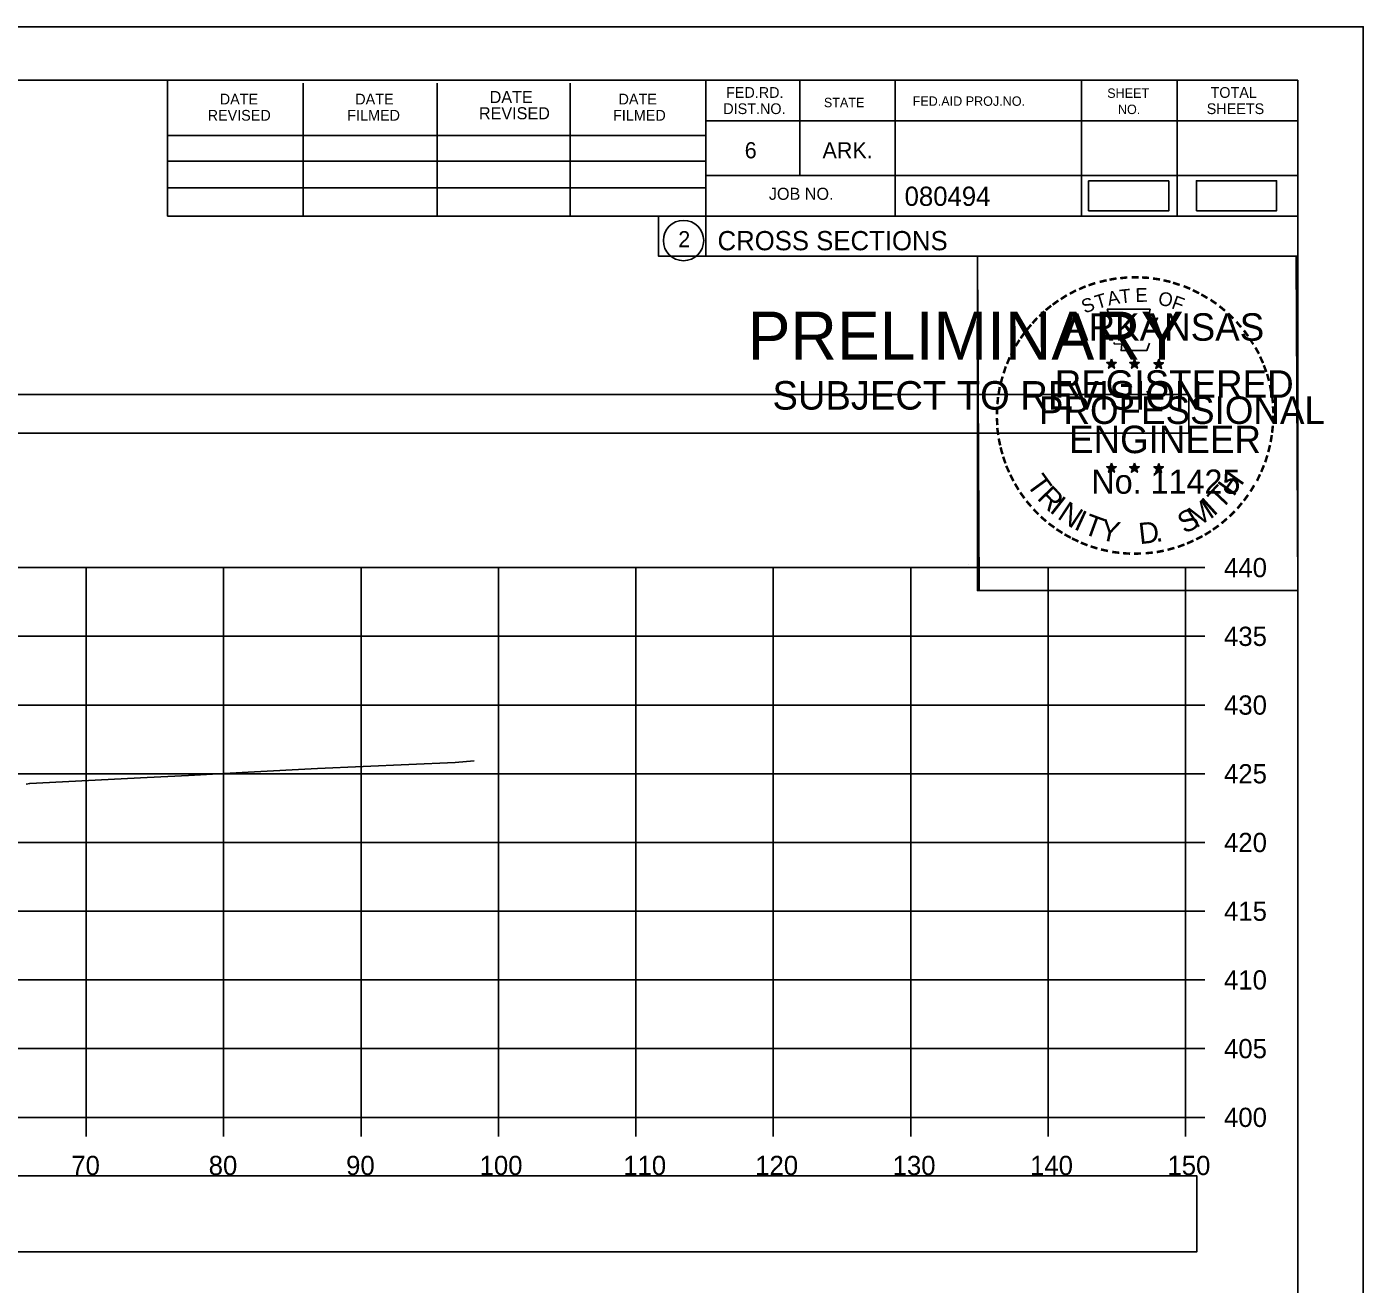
# Model space of a CAD drawing. Extents: x 1376273 to 1384221, y 378927 to 384592.
# Drawn here: x 1378290.1 to 1378387.4, y 382153.7 to 382245.2 of the extents above; entities that cross this region are included whole.
import ezdxf

# ---------------------------------------------------------------- set-up
doc = ezdxf.new("R2010")
doc.units = 0
for name, color, linetype in [('R_Axis', 7, 'Continuous'), ('R_Axis Annot', 7, 'Continuous'), ('R_Border', 7, 'Continuous'), ('R_Border PE', 7, 'Continuous'), ('R_Border Prem', 7, 'Continuous'), ('R_Drive', 7, 'Continuous'), ('R_Exist Surface', 7, 'Continuous'), ('R_Grid', 7, 'Continuous'), ('R_No Plot', 7, 'Continuous')]:
    doc.layers.add(name, color=color, linetype=linetype)

msp = doc.modelspace()

# ---------------------------------------------------------------- linework, layer by layer
at = {"layer": 'R_Axis'}
for p, q in [((1378374.457, 382165.86), (1378374.457, 382205.86)), ((1378375.857, 382205.86), (1378374.457, 382205.86)), ((1378375.857, 382200.86), (1378374.457, 382200.86)), ((1378375.857, 382195.86), (1378374.457, 382195.86)), ((1378375.857, 382190.86), (1378374.457, 382190.86)), ((1378375.857, 382185.86), (1378374.457, 382185.86)), ((1378375.857, 382180.86), (1378374.457, 382180.86)), ((1378375.857, 382175.86), (1378374.457, 382175.86)), ((1378375.857, 382170.86), (1378374.457, 382170.86)), ((1378074.457, 382165.86), (1378374.457, 382165.86)), ((1378294.457, 382164.46), (1378294.457, 382165.86)), ((1378304.457, 382164.46), (1378304.457, 382165.86)), ((1378314.457, 382164.46), (1378314.457, 382165.86)), ((1378324.457, 382164.46), (1378324.457, 382165.86)), ((1378334.457, 382164.46), (1378334.457, 382165.86)), ((1378344.457, 382164.46), (1378344.457, 382165.86)), ((1378354.457, 382164.46), (1378354.457, 382165.86)), ((1378364.457, 382164.46), (1378364.457, 382165.86)), ((1378374.457, 382164.46), (1378374.457, 382165.86)), ((1378375.857, 382165.86), (1378374.457, 382165.86))]:
    msp.add_line(p, q, dxfattribs=at)
at = {"layer": 'R_Axis Annot'}
for points in [[(1378072.9, 382215.644), (1378374.702, 382215.644), (1378374.702, 382218.461), (1378072.9, 382218.461)], [(1378073.479, 382156.081), (1378375.281, 382156.081), (1378375.281, 382161.603), (1378073.479, 382161.603)]]:
    msp.add_lwpolyline(points, close=True, dxfattribs=at)
at = {"layer": 'R_Border'}
for p, q in [((1378066.457, 382241.32), (1378382.637, 382241.32)), ((1378300.377, 382231.44), (1378300.377, 382241.32)), ((1378310.237, 382231.44), (1378310.237, 382241.12)), ((1378319.997, 382231.44), (1378319.997, 382241.12)), ((1378329.677, 382231.44), (1378329.677, 382241.12)), ((1378339.537, 382241.32), (1378339.537, 382228.52)), ((1378346.377, 382241.32), (1378346.377, 382234.38)), ((1378353.317, 382241.32), (1378353.317, 382231.44)), ((1378366.897, 382241.32), (1378366.897, 382231.44)), ((1378373.837, 382241.32), (1378373.837, 382231.44)), ((1378382.637, 382035.86), (1378382.637, 382241.32)), ((1378382.637, 382238.38), (1378339.537, 382238.38)), ((1378382.637, 382238.4), (1378382.637, 382238.4)), ((1378300.377, 382237.3), (1378339.537, 382237.3)), ((1378300.377, 382235.44), (1378339.537, 382235.44)), ((1378382.637, 382234.38), (1378339.537, 382234.38)), ((1378342.497, 382234.38), (1378382.637, 382234.38)), ((1378300.377, 382231.44), (1378300.377, 382233.5)), ((1378300.377, 382233.5), (1378339.537, 382233.5)), ((1378382.637, 382231.44), (1378300.377, 382231.44)), ((1378339.537, 382228.52), (1378382.637, 382228.52))]:
    msp.add_line(p, q, dxfattribs=at)
msp.add_circle((1378337.924, 382229.656), 1.467, dxfattribs=at)
at = {"layer": 'R_Border PE'}
for p, q in [((1378368.722, 382220.776), (1378369.071, 382220.665)), ((1378368.722, 382220.776), (1378368.975, 382220.731)), ((1378368.722, 382220.776), (1378368.959, 382220.654)), ((1378368.855, 382220.368), (1378369.071, 382220.665)), ((1378368.855, 382220.368), (1378368.981, 382220.612)), ((1378368.855, 382220.368), (1378369.069, 382220.585)), ((1378369.071, 382221.03), (1378369.03, 382220.778)), ((1378369.284, 382220.368), (1378369.069, 382220.582)), ((1378369.071, 382220.665), (1378369.071, 382221.03)), ((1378369.071, 382221.03), (1378369.12, 382220.78)), ((1378369.418, 382220.776), (1378369.071, 382220.665)), ((1378369.284, 382220.368), (1378369.071, 382220.665)), ((1378369.418, 382220.776), (1378369.132, 382220.727)), ((1378369.284, 382220.368), (1378369.147, 382220.659)), ((1378369.418, 382220.776), (1378369.214, 382220.674)), ((1378370.392, 382220.776), (1378370.741, 382220.665)), ((1378370.392, 382220.776), (1378370.645, 382220.731)), ((1378370.392, 382220.776), (1378370.629, 382220.654)), ((1378370.525, 382220.368), (1378370.741, 382220.665)), ((1378370.525, 382220.368), (1378370.651, 382220.612)), ((1378370.525, 382220.368), (1378370.739, 382220.585)), ((1378370.741, 382221.03), (1378370.7, 382220.778)), ((1378370.954, 382220.368), (1378370.739, 382220.582)), ((1378370.741, 382220.665), (1378370.741, 382221.03)), ((1378370.741, 382221.03), (1378370.79, 382220.78)), ((1378371.088, 382220.776), (1378370.741, 382220.665)), ((1378370.954, 382220.368), (1378370.741, 382220.665)), ((1378371.088, 382220.776), (1378370.802, 382220.727)), ((1378370.954, 382220.368), (1378370.817, 382220.659)), ((1378371.088, 382220.776), (1378370.884, 382220.674)), ((1378372.156, 382220.764), (1378372.505, 382220.653)), ((1378372.156, 382220.764), (1378372.409, 382220.719)), ((1378372.156, 382220.764), (1378372.393, 382220.642)), ((1378372.289, 382220.356), (1378372.505, 382220.653)), ((1378372.289, 382220.356), (1378372.415, 382220.6)), ((1378372.289, 382220.356), (1378372.503, 382220.573)), ((1378372.505, 382221.018), (1378372.464, 382220.766)), ((1378372.718, 382220.356), (1378372.503, 382220.57)), ((1378372.505, 382220.653), (1378372.505, 382221.018)), ((1378372.505, 382221.018), (1378372.554, 382220.768)), ((1378372.852, 382220.764), (1378372.505, 382220.653)), ((1378372.718, 382220.356), (1378372.505, 382220.653)), ((1378372.852, 382220.764), (1378372.566, 382220.715)), ((1378372.718, 382220.356), (1378372.581, 382220.647)), ((1378372.852, 382220.764), (1378372.648, 382220.662)), ((1378369.067, 382213.457), (1378369.026, 382213.205)), ((1378369.067, 382213.092), (1378369.067, 382213.457)), ((1378369.067, 382213.457), (1378369.116, 382213.207)), ((1378370.736, 382213.457), (1378370.695, 382213.205)), ((1378370.736, 382213.092), (1378370.736, 382213.457)), ((1378370.736, 382213.457), (1378370.785, 382213.207)), ((1378372.503, 382213.447), (1378372.462, 382213.195)), ((1378372.503, 382213.082), (1378372.503, 382213.447)), ((1378372.503, 382213.447), (1378372.552, 382213.197)), ((1378368.718, 382213.203), (1378369.067, 382213.092)), ((1378368.718, 382213.203), (1378368.971, 382213.158)), ((1378368.718, 382213.203), (1378368.955, 382213.081)), ((1378368.851, 382212.795), (1378369.067, 382213.092)), ((1378368.851, 382212.795), (1378368.977, 382213.039)), ((1378368.851, 382212.795), (1378369.065, 382213.012)), ((1378369.28, 382212.795), (1378369.065, 382213.009)), ((1378369.414, 382213.203), (1378369.067, 382213.092)), ((1378369.28, 382212.795), (1378369.067, 382213.092)), ((1378369.414, 382213.203), (1378369.128, 382213.154)), ((1378369.28, 382212.795), (1378369.143, 382213.086)), ((1378369.414, 382213.203), (1378369.21, 382213.101)), ((1378370.387, 382213.203), (1378370.736, 382213.092)), ((1378370.387, 382213.203), (1378370.64, 382213.158)), ((1378370.387, 382213.203), (1378370.624, 382213.081)), ((1378370.52, 382212.795), (1378370.736, 382213.092)), ((1378370.52, 382212.795), (1378370.646, 382213.039)), ((1378370.52, 382212.795), (1378370.734, 382213.012)), ((1378370.949, 382212.795), (1378370.734, 382213.009)), ((1378371.083, 382213.203), (1378370.736, 382213.092)), ((1378370.949, 382212.795), (1378370.736, 382213.092)), ((1378371.083, 382213.203), (1378370.797, 382213.154)), ((1378370.949, 382212.795), (1378370.812, 382213.086)), ((1378371.083, 382213.203), (1378370.879, 382213.101)), ((1378372.154, 382213.193), (1378372.503, 382213.082)), ((1378372.154, 382213.193), (1378372.407, 382213.148)), ((1378372.154, 382213.193), (1378372.391, 382213.071)), ((1378372.287, 382212.785), (1378372.503, 382213.082)), ((1378372.287, 382212.785), (1378372.413, 382213.029)), ((1378372.287, 382212.785), (1378372.501, 382213.002)), ((1378372.716, 382212.785), (1378372.501, 382212.999)), ((1378372.85, 382213.193), (1378372.503, 382213.082)), ((1378372.716, 382212.785), (1378372.503, 382213.082)), ((1378372.85, 382213.193), (1378372.564, 382213.144)), ((1378372.716, 382212.785), (1378372.579, 382213.076)), ((1378372.85, 382213.193), (1378372.646, 382213.091))]:
    msp.add_line(p, q, dxfattribs=at)
for points in [[(1378368.763, 382224.654), (1378369.032, 382223.827)], [(1378372.274, 382223.732), (1378372.416, 382224.016), (1378371.731, 382223.992), (1378371.879, 382224.654), (1378368.763, 382224.654)], [(1378369.255, 382222.231), (1378369.255, 382222.144), (1378369.818, 382222.125), (1378369.764, 382221.652), (1378371.634, 382221.652), (1378371.835, 382222.188)], [(1378369.071, 382221.03), (1378369.284, 382220.368), (1378368.722, 382220.776), (1378369.418, 382220.776), (1378368.855, 382220.368), (1378369.071, 382221.03)], [(1378370.741, 382221.03), (1378370.954, 382220.368), (1378370.392, 382220.776), (1378371.088, 382220.776), (1378370.525, 382220.368), (1378370.741, 382221.03)], [(1378372.505, 382221.018), (1378372.718, 382220.356), (1378372.156, 382220.764), (1378372.852, 382220.764), (1378372.289, 382220.356), (1378372.505, 382221.018)], [(1378369.067, 382213.457), (1378369.28, 382212.795), (1378368.718, 382213.203), (1378369.414, 382213.203), (1378368.851, 382212.795), (1378369.067, 382213.457)], [(1378370.736, 382213.457), (1378370.949, 382212.795), (1378370.387, 382213.203), (1378371.083, 382213.203), (1378370.52, 382212.795), (1378370.736, 382213.457)], [(1378372.503, 382213.447), (1378372.716, 382212.785), (1378372.154, 382213.193), (1378372.85, 382213.193), (1378372.287, 382212.785), (1378372.503, 382213.447)]]:
    msp.add_lwpolyline(points, dxfattribs=at)
for centre, radius in [((1378369.07, 382220.664), 0.172), ((1378369.07, 382220.664), 0.145), ((1378369.07, 382220.664), 0.116), ((1378369.07, 382220.664), 0.0991), ((1378369.07, 382220.664), 0.0747), ((1378369.07, 382220.664), 0.0495), ((1378369.07, 382220.664), 0.0296), ((1378370.74, 382220.664), 0.172), ((1378370.74, 382220.664), 0.145), ((1378370.74, 382220.664), 0.116), ((1378370.74, 382220.664), 0.0991), ((1378370.74, 382220.664), 0.0747), ((1378370.74, 382220.664), 0.0495), ((1378370.74, 382220.664), 0.0296), ((1378372.504, 382220.652), 0.172), ((1378372.504, 382220.652), 0.145), ((1378372.504, 382220.652), 0.116), ((1378372.504, 382220.652), 0.0991), ((1378372.504, 382220.652), 0.0747), ((1378372.504, 382220.652), 0.0495), ((1378372.504, 382220.652), 0.0296), ((1378369.066, 382213.091), 0.172), ((1378369.066, 382213.091), 0.145), ((1378369.066, 382213.091), 0.116), ((1378369.066, 382213.091), 0.0991), ((1378369.066, 382213.091), 0.0747), ((1378369.066, 382213.091), 0.0495), ((1378369.066, 382213.091), 0.0296), ((1378370.735, 382213.091), 0.172), ((1378370.735, 382213.091), 0.145), ((1378370.735, 382213.091), 0.116), ((1378370.735, 382213.091), 0.0991), ((1378370.735, 382213.091), 0.0747), ((1378370.735, 382213.091), 0.0495), ((1378370.735, 382213.091), 0.0296), ((1378372.502, 382213.081), 0.172), ((1378372.502, 382213.081), 0.145), ((1378372.502, 382213.081), 0.116), ((1378372.502, 382213.081), 0.0991), ((1378372.502, 382213.081), 0.0747), ((1378372.502, 382213.081), 0.0495), ((1378372.502, 382213.081), 0.0296)]:
    msp.add_circle(centre, radius, dxfattribs=at)
at = {"layer": 'R_Drive'}
for points in [[(1378367.399, 382231.809), (1378373.232, 382231.809), (1378373.232, 382233.996), (1378367.399, 382233.996)], [(1378375.245, 382231.82), (1378381.078, 382231.82), (1378381.078, 382234.006), (1378375.245, 382234.006)]]:
    msp.add_lwpolyline(points, close=True, dxfattribs=at)
at = {"layer": 'R_Exist Surface'}
msp.add_lwpolyline([(1378290.084, 382190.096), (1378290.346, 382190.161), (1378298.906, 382190.592), (1378301.901, 382190.739), (1378306.238, 382190.981), (1378311.294, 382191.253), (1378317.93, 382191.53), (1378321.307, 382191.671), (1378322.702, 382191.806)], dxfattribs=at)
at = {"layer": 'R_Grid'}
for p, q in [((1378074.457, 382205.86), (1378374.457, 382205.86)), ((1378294.457, 382165.86), (1378294.457, 382205.86)), ((1378304.457, 382165.86), (1378304.457, 382205.86)), ((1378314.457, 382165.86), (1378314.457, 382205.86)), ((1378324.457, 382165.86), (1378324.457, 382205.86)), ((1378334.457, 382165.86), (1378334.457, 382205.86)), ((1378344.457, 382165.86), (1378344.457, 382205.86)), ((1378354.457, 382165.86), (1378354.457, 382205.86)), ((1378364.457, 382165.86), (1378364.457, 382205.86)), ((1378374.457, 382165.86), (1378374.457, 382205.86)), ((1378074.457, 382200.86), (1378374.457, 382200.86)), ((1378074.457, 382195.86), (1378374.457, 382195.86)), ((1378074.457, 382190.86), (1378374.457, 382190.86)), ((1378074.457, 382185.86), (1378374.457, 382185.86)), ((1378074.457, 382180.86), (1378374.457, 382180.86)), ((1378074.457, 382175.86), (1378374.457, 382175.86)), ((1378074.457, 382170.86), (1378374.457, 382170.86)), ((1378074.457, 382165.86), (1378374.457, 382165.86))]:
    msp.add_line(p, q, dxfattribs=at)
at = {"layer": 'R_No Plot'}
for p, q in [((1378054.056, 382245.215), (1378387.39, 382245.215)), ((1378358.671, 382206.065), (1378358.671, 382206.065))]:
    msp.add_line(p, q, dxfattribs=at)
for points in [[(1378054.05, 382245.215), (1378387.39, 382245.215), (1378387.39, 382031.877), (1378054.05, 382031.877)], [(1378300.377, 382241.32), (1378300.377, 382231.44), (1378336.109, 382231.44), (1378336.109, 382228.52), (1378359.309, 382228.52), (1378359.309, 382204.188), (1378382.637, 382204.188), (1378382.637, 382035.86), (1378066.457, 382035.86), (1378066.457, 382241.32)], [(1378359.309, 382228.52), (1378382.516, 382228.52), (1378382.637, 382204.188), (1378359.429, 382204.188)]]:
    msp.add_lwpolyline(points, close=True, dxfattribs=at)

# ---------------------------------------------------------------- texts
at = {"layer": 'R_Axis Annot'}
for s, p in [('440', (1378377.257, 382205.16)), ('435', (1378377.257, 382200.16)), ('430', (1378377.257, 382195.16)), ('425', (1378377.257, 382190.16)), ('420', (1378377.257, 382185.16)), ('415', (1378377.257, 382180.16)), ('410', (1378377.257, 382175.16)), ('405', (1378377.257, 382170.16)), ('400', (1378377.257, 382165.16)), ('70', (1378293.371, 382161.66)), ('80', (1378303.371, 382161.66)), ('90', (1378313.371, 382161.66)), ('100', (1378323.085, 382161.66)), ('110', (1378333.537, 382161.66)), ('120', (1378343.14, 382161.66)), ('130', (1378353.14, 382161.66)), ('140', (1378363.14, 382161.66)), ('150', (1378373.14, 382161.66))]:
    msp.add_text(s, height=1.4, dxfattribs=at).set_placement(p)
at = {"layer": 'R_Border'}
for s, height, p in [('FED.RD.', 0.7819, (1378341.017, 382240.04)), ('SHEET', 0.684, (1378368.757, 382240.04)), ('TOTAL', 0.7819, (1378376.277, 382240.04)), ('DATE', 0.7819, (1378304.177, 382239.56)), ('DATE', 0.7819, (1378314.037, 382239.56)), ('DATE', 0.8792, (1378323.817, 382239.66)), ('DATE', 0.7819, (1378333.197, 382239.56)), ('DIST.NO.', 0.7819, (1378340.817, 382238.86)), ('STATE', 0.684, (1378348.137, 382239.36)), ('FED.AID PROJ.NO.', 0.684, (1378354.597, 382239.46)), ('SHEETS', 0.7819, (1378375.997, 382238.86)), ('REVISED', 0.7819, (1378303.297, 382238.38)), ('FILMED', 0.7819, (1378313.457, 382238.38)), ('REVISED', 0.8792, (1378323.037, 382238.48)), ('FILMED', 0.7819, (1378332.797, 382238.38)), ('NO.', 0.684, (1378369.537, 382238.86)), ('6', 1.172, (1378342.377, 382235.64)), ('ARK.', 1.1723, (1378348.037, 382235.64)), ('JOB NO.', 0.8792, (1378344.137, 382232.62)), ('080494', 1.4, (1378354.013, 382232.18)), ('2', 1.172, (1378337.541, 382229.17)), ('CROSS SECTIONS', 1.4, (1378340.401, 382228.95))]:
    msp.add_text(s, height=height, rotation=360, dxfattribs=at).set_placement(p)
at = {"layer": 'R_Border PE'}
for s, height, rotation, p in [('-', 1.6, 10.21935, (1378368.939, 382226.184)), ('-', 1.6, 5.89682, (1378369.668, 382226.294)), ('-', 1.6, 0.18623, (1378370.44, 382226.366)), ('-', 1.6, 357.74304, (1378371.163, 382226.353)), ('-', 1.6, 352.16172, (1378371.907, 382226.297)), ('-', 1.6, 28.79182, (1378366.244, 382225.195)), ('-', 1.6, 24.30721, (1378366.877, 382225.512)), ('-', 1.6, 19.17608, (1378367.511, 382225.781)), ('-', 1.6, 13.63015, (1378368.261, 382226.022)), ('A', 1, 11.21318, (1378368.858, 382224.914)), ('T', 1, 6.02276, (1378369.707, 382225.08)), ('E', 1, 0.83234, (1378370.812, 382225.19)), ('-', 1.6, 347.20489, (1378372.626, 382226.183)), ('-', 1.6, 342.3362, (1378373.261, 382226.028)), ('-', 1.6, 337.85509, (1378373.996, 382225.805)), ('-', 1.6, 334.12109, (1378374.627, 382225.534)), ('-', 1.6, 36.23174, (1378365.069, 382224.43)), ('-', 1.6, 34.06357, (1378365.647, 382224.825)), ('S', 1, 21.59401, (1378367.118, 382224.332)), ('T', 1, 16.4036, (1378368.032, 382224.663)), ('O', 1, 350.4515, (1378372.416, 382224.98)), ('F', 1, 340.07066, (1378373.37, 382224.752)), ('-', 1.6, 329.64089, (1378375.206, 382225.251)), ('-', 1.6, 325.86266, (1378375.849, 382224.89)), ('-', 1.6, 48.42305, (1378363.712, 382223.157)), ('-', 1.6, 42.96224, (1378364.16, 382223.635)), ('-', 1.6, 38.95066, (1378364.593, 382224.052)), ('ARKANSAS', 2, 360, (1378365.616, 382222.366)), ('-', 1.6, 320.52971, (1378376.459, 382224.464)), ('-', 1.6, 315.57859, (1378377.058, 382223.976)), ('-', 1.6, 50.61417, (1378363.309, 382222.671)), ('-', 1.6, 309.87973, (1378377.627, 382223.426)), ('-', 1.6, 306.65218, (1378378.152, 382222.824)), ('-', 1.6, 58.07063, (1378362.571, 382221.577)), ('-', 1.6, 54.23247, (1378362.896, 382222.104)), ('-', 1.4, 303.67529, (1378378.638, 382222.256)), ('-', 1.6, 67.77427, (1378361.999, 382220.352)), ('-', 1.6, 62.87135, (1378362.258, 382220.963)), ('-', 1.6, 299.66835, (1378378.957, 382221.649)), ('-', 1.6, 294.66279, (1378379.281, 382221.037)), ('-', 1.6, 72.39447, (1378361.78, 382219.722)), ('REGISTERED', 2, 360, (1378364.938, 382218.217)), ('DWB', 0.01, 360, (1378369.058, 382220.659)), ('DWB', 0.01, 360, (1378370.728, 382220.659)), ('DWB', 0.01, 360, (1378372.492, 382220.648)), ('-', 1.6, 290.57283, (1378379.538, 382220.46)), ('-', 1.6, 75.46096, (1378361.583, 382219.008)), ('-', 1.6, 285.12326, (1378379.772, 382219.88)), ('-', 1.6, 85.18634, (1378361.375, 382217.604)), ('-', 1.6, 81.20126, (1378361.451, 382218.295)), ('PROFESSIONAL', 2, 360, (1378363.79, 382216.313)), ('-', 1.6, 280.54934, (1378379.972, 382219.138)), ('-', 1.6, 276.59616, (1378380.134, 382218.37)), ('-', 1.6, 89.06224, (1378361.35, 382216.903)), ('-', 1.6, 274.33011, (1378380.194, 382217.648)), ('-', 1.6, 94.19588, (1378361.385, 382216.178)), ('-', 1.6, 269.94067, (1378380.228, 382217.016)), ('-', 1.6, 98.94793, (1378361.457, 382215.511)), ('ENGINEER', 2, 360, (1378365.977, 382214.188)), ('-', 1.6, 260.99529, (1378380.138, 382215.696)), ('-', 1.6, 263.5172, (1378380.209, 382216.35)), ('-', 1.6, 101.71495, (1378361.592, 382214.778)), ('-', 1.6, 105.45785, (1378361.754, 382214.183)), ('-', 1.6, 255.7626, (1378380.028, 382215.018)), ('-', 1.6, 109.08742, (1378361.969, 382213.552)), ('-', 1.6, 252.86809, (1378379.847, 382214.298)), ('-', 1.6, 114.06432, (1378362.223, 382212.956)), ('-', 1.6, 115.72885, (1378362.528, 382212.338)), ('T', 1.54, 306.04056, (1378362.827, 382211.93)), ('No. 11425', 1.757, 360, (1378367.604, 382211.237)), ('DWB', 0.01, 360, (1378369.054, 382213.086)), ('DWB', 0.01, 360, (1378370.723, 382213.087)), ('DWB', 0.01, 360, (1378372.49, 382213.077)), ('H', 1.54, 54.60883, (1378377.947, 382210.965)), ('-', 1.6, 244.61971, (1378379.362, 382212.996)), ('-', 1.6, 247.88866, (1378379.624, 382213.625)), ('-', 1.6, 120.44712, (1378362.885, 382211.752)), ('R', 1.54, 314.00497, (1378363.589, 382210.882)), ('T', 1.54, 46.64442, (1378377.057, 382210.022)), ('-', 1.6, 239.07125, (1378378.968, 382212.244)), ('-', 1.6, 125.89344, (1378363.288, 382211.191)), ('-', 1.6, 130.71812, (1378363.75, 382210.639)), ('I', 1.54, 321.96938, (1378364.49, 382209.95)), ('N', 1.54, 326.50021, (1378365.057, 382209.478)), ('M', 1.54, 32.65632, (1378375.211, 382208.697)), ('I', 1.54, 42.11359, (1378376.496, 382209.544)), ('-', 1.6, 231.25377, (1378378.136, 382211.025)), ('-', 1.6, 233.84524, (1378378.566, 382211.591)), ('-', 1.6, 134.22381, (1378364.267, 382210.094)), ('-', 1.6, 138.93382, (1378364.792, 382209.63)), ('I', 1.54, 335.36034, (1378366.265, 382208.692)), ('T', 1.54, 339.89117, (1378366.926, 382208.365)), ('S', 1.54, 26.9312, (1378374.373, 382208.291)), ('-', 1.6, 221.08509, (1378377.135, 382209.952)), ('-', 1.6, 225.76533, (1378377.657, 382210.461)), ('-', 1.6, 144.64634, (1378365.348, 382209.224)), ('-', 1.6, 148.08978, (1378365.909, 382208.853)), ('Y', 1.54, 347.85558, (1378368.143, 382207.919)), ('D', 1.54, 6.39691, (1378371.128, 382207.561)), ('-', 1.6, 212.24909, (1378376.052, 382209.093)), ('-', 1.6, 215.73633, (1378376.586, 382209.48)), ('-', 1.6, 151.57039, (1378366.488, 382208.528)), ('-', 1.6, 154.60019, (1378367.01, 382208.281)), ('-', 1.6, 158.56121, (1378367.634, 382208.027)), ('.', 1.54, 13.76417, (1378372.32, 382207.688)), ('-', 1.6, 200.71842, (1378374.251, 382208.155)), ('-', 1.6, 204.25161, (1378374.87, 382208.428)), ('-', 1.6, 207.35684, (1378375.494, 382208.747)), ('-', 1.6, 162.79826, (1378368.321, 382207.814)), ('-', 1.6, 167.55551, (1378369.036, 382207.65)), ('-', 1.6, 173.11546, (1378369.808, 382207.54)), ('-', 1.6, 176.51827, (1378370.556, 382207.487)), ('-', 1.6, 181.59176, (1378371.3, 382207.506)), ('-', 1.6, 185.81666, (1378372.109, 382207.582)), ('-', 1.6, 191.28576, (1378372.845, 382207.714)), ('-', 1.6, 195.47429, (1378373.574, 382207.913))]:
    msp.add_text(s, height=height, rotation=rotation, dxfattribs=at).set_placement(p)
at = {"layer": 'R_Border Prem'}
for s, height, p in [('PRELIMINARY', 3.5, (1378342.588, 382220.984)), ('DWB', 0.01, (1378343.335, 382222.833)), ('SUBJECT TO REVISION', 2.07511, (1378344.397, 382217.355))]:
    msp.add_text(s, height=height, rotation=360, dxfattribs=at).set_placement(p)

doc.saveas('drawing.dxf')
